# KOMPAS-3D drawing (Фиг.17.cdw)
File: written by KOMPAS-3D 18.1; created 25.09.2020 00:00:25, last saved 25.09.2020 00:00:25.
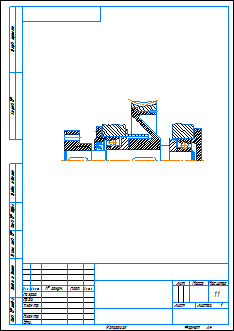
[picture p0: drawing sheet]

Sheet 1: A4, portrait

Document properties: Автор: user; Полное имя файла: C:\Users\user\Desktop\Задания\Фиг.17.cdw

Title block, sheet 1: scale: 1:1; Количество листов документа: 1; Форматы листов документа: A4

Dimensions and other numbers on the sheet: 1:1; 1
